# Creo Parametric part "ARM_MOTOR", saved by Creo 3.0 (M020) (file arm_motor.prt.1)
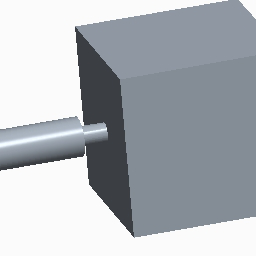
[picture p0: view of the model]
Units: millimeter Newton Second (mmNs); MM, TONNE, SECS

Created from: MMNS_PART_SOLID.PRT

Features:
  1. datum plane "RIGHT"
  2. datum plane "TOP"
  3. datum plane "FRONT"
  4. coordinate system
  5. sketch "Sketch 1"
  6. extrusion "Extrude 1"
  7. sketch "Sketch 2"
  8. extrusion "Extrude 2"
  9. sketch "Sketch 3"
  10. extrusion "Extrude 3"

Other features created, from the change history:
  sketch "Sketch 3"
  extrusion "Extrude 3"

Surfaces: 11 plane, 4 cylinder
